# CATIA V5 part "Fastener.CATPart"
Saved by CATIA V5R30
Part number: Fastener
Bounding box of the stored display mesh (mm): x -5 to 5, y -5 to 5, z -48 to 0
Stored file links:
  D:\PROJECTS\CATIA V56R 2020\Resources\c14\c14tut2\c14tut2.CATParts\Fastener.CATPart
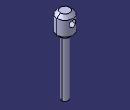
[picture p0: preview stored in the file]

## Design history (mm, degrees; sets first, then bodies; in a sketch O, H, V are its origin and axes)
Body1 (main body)
  Sketch1 on xy-plane, origin (0, 0, 0), H (1, 0, 0), V (0, 1, 0)
    circle A1 centre (0, 0) radius 5
    circle A2 centre (0, 0) radius 2
    radius A2 = 2
    radius A1 = 5
  MultiPad1: profile Sketch1, domains (length 0 / length 48; length 0 / length 13)
  Chamfer1: length 2, angle 45, on 2 edges
  Chamfer2: length 0.508, angle 45, on 1 edge
  Sketch2 on zx-plane, origin (-1.612, 0, 1.612), H (1, 0, 0), V (0, 0, -1)
    point P1 (1.612, 6.35)
    reference intersected line E1 through (1.612, 0) direction (0, 1) from yz-plane
    distance P1 H = 6.35
    coincidence: E1 P1
  Hole1: placed by Sketch2, at (0, 0, -4.738) direction (0, -1, 0), diameter 4, depth 10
